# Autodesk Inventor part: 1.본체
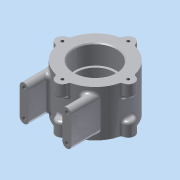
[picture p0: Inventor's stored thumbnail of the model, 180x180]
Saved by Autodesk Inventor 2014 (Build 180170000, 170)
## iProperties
Created: 2015-03
Part Number: 1.본체
Material: 알루미늄 6061
Document SubType Name: Modeling
Designer: net
Density: 2.71 g/cm^3
Appearance: 알루미늄 - 평지
Mass: 450.776 g
Surface Area: 332.745 cm^2
Volume: 166.338 cm^3
Author: net
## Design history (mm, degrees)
sketch "스케치1"
  geometry: C1 r 37 at (0, 0); 1 further point
  constraints: 1 centre point, 1 coincident
  dimensions: "d0" = 74 diameter of C1
extrude "돌출1" new body sketch "스케치1" stored distance "d1" = 52; taper "d2" = 0 deg
sketch "스케치2"
  geometry: C1 r 7 at (0, 37); C2 r 7 at (37, 0); C3 r 7 at (0, -37); C4 r 7 at (-37, 0); A1 r 37 centre (0, 0) between (0, 37) and (37, 0) reference
  constraints: 4 centre point, 4 point on circle, 3 equal radius, 2 horizontal alignment, 2 vertical alignment
  dimensions: "d3" = 14 diameter of C1
extrude "돌출2" join sketch "스케치2" distance "d4" = 15; taper "d5" = 0 deg
hole "구멍1" diameter "d8" = 3.242; stored, may be unused: countersink angle "d12" = 90 deg, drill point angle "d14" = 118 deg; dims "d6" = 10, "d7" = 10, "d9" = 8, "d10" = 4, "d11" = 2, "d13" = 11
node "작업 평면1"
node "작업 평면2"
sketch "스케치3"
  geometry: L1 (0, 0)-(-26.163, 26.163); L2 (0, 0)-(-37, 0); A1 r 37 centre (0, 0) between (-6.969, 36.338) and (-36.338, 6.969) reference; 2 further points
  constraints: 4 end point, 1 coincident, 1 horizontal, 1 point on circle
  dimensions: "d18" = 45 deg angle of L2 L1
node "작업 평면3"
sketch "스케치4"
  geometry: L1 (-20.767, -26)-(20.767, -26) reference; 2 further points
  constraints: 1 coincident, 1 other
  dimensions: "d92" = 26 distance from line of point (0, 0) L1
feature "엠보싱1" sketch "스케치4" dims "d1" = 52, "d19" = 0.5, "d20" = 0
node "작업 평면4"
sketch "스케치5"
  geometry: L1 (19, -15)-(19, 15); L2 (29, -15)-(29, 15); L3 (-29, 15)-(-29, -15); L4 (-19, -15)-(-19, 15); A1 r 5 centre (24, 15) between (19, 15) and (29, 15); A2 r 5 centre (24, -15) between (19, -15) and (29, -15); A3 r 5 centre (-24, -15) between (-29, -15) and (-19, -15); A4 r 5 centre (-24, 15) between (-29, 15) and (-19, 15); 2 further points
  constraints: 8 end point, 8 point on circle, 7 tangent, 4 centre point, 2 vertical alignment, 1 horizontal alignment, 1 midpoint, 1 parallel
  dimensions: "d22" = 10 diameter of A1; "d23" = 10 diameter of A2; "d24" = 30 distance of A2.centre A1.centre; "d25" = 24 horizontal distance of A2.centre point (0, 0); "d29" = 10 diameter of A4; "d30" = 10 diameter of A3; "d31" = 30 distance of A3.centre A4.centre; "d32" = 24 horizontal distance of point (0, 0) A3.centre; "d35" = 24.20744 distance of L4.end point (0, 0)
extrude "돌출3" join sketch "스케치5" stored distance "d36" = 15; taper "d37" = 0 deg
hole "구멍2" diameter "d40" = 4.134; stored, may be unused: countersink angle "d44" = 90 deg, drill point angle "d46" = 118 deg; dims "d38" = 10, "d39" = 10, "d41" = 6, "d42" = 4, "d43" = 2, "d45" = 8
hole "구멍3" diameter "d49" = 4.134; stored, may be unused: countersink angle "d53" = 90 deg, drill point angle "d55" = 118 deg; dims "d47" = 10, "d48" = 10, "d50" = 6, "d51" = 4, "d52" = 2, "d54" = 8
hole "구멍4" diameter "d58" = 4.134; stored, may be unused: countersink angle "d62" = 90 deg, drill point angle "d64" = 118 deg; dims "d56" = 10, "d57" = 10, "d59" = 6, "d60" = 4, "d61" = 2, "d63" = 8
hole "구멍5" diameter "d67" = 4.134; stored, may be unused: countersink angle "d71" = 90 deg, drill point angle "d73" = 118 deg; dims "d65" = 10, "d66" = 10, "d68" = 6, "d69" = 4, "d70" = 2, "d72" = 8
hole "구멍6" diameter "d76" = 47; stored, may be unused: countersink angle "d80" = 90 deg, drill point angle "d82" = 0 deg; dims "d74" = 10, "d75" = 10, "d77" = 6, "d78" = 4, "d79" = 2, "d81" = 22
hole "구멍7" diameter "d85" = 42; stored, may be unused: countersink angle "d89" = 90 deg, drill point angle "d91" = 0 deg; dims "d83" = 10, "d84" = 10, "d86" = 6, "d87" = 47, "d88" = 22, "d90" = 50
fillet "모깎기1" dims "d93" = 0.3
chamfer "모따기1" distance "d94" = 1; stored, may be unused: second distance "d95" = 2, angle "d96" = 45 deg
fillet "모깎기2" dims "d97" = 3
fillet "모깎기3" dims "d98" = 3
fillet "모깎기4" dims "d99" = 3
fillet "모깎기5" dims "d100" = 3
fillet "모깎기6" dims "d101" = 3
fillet "모깎기7" dims "d102" = 3
node "솔리드1"
pattern_circular "원형 패턴1" dims angle "d16" = 360 deg
mirror "대칭1"
other parameters: "d21" = -56
